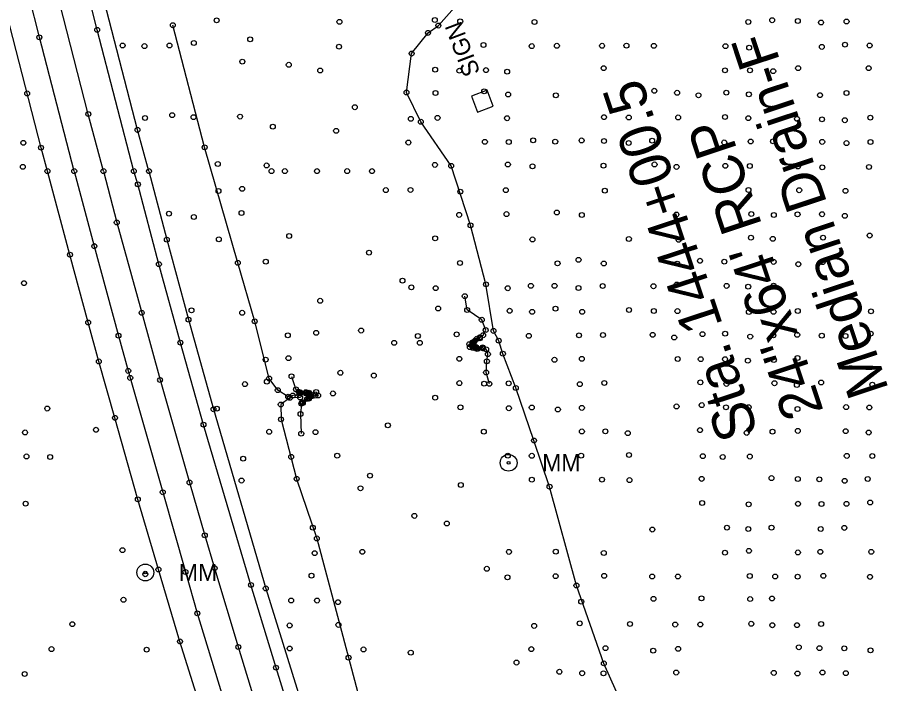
# Model space of a CAD drawing. Extents: x 20503438 to 20508873, y 7964251 to 7984667.
# Drawn here: x 20505592.1 to 20505946.9, y 7976920.6 to 7977192.3 of the extents above; entities that cross this region are included whole.
import ezdxf

# ---------------------------------------------------------------- set-up
doc = ezdxf.new("R2010")
doc.units = 0
for name, color, linetype in [('SurBreakLine', 7, 'Continuous'), ('SurConcreteSlab', 7, 'Continuous'), ('SurDrainageArrowUp', 7, 'Continuous'), ('SurEdgeRoadPaved', 7, 'Continuous'), ('SurEdgeShoulderPaved', 7, 'Continuous'), ('SurPointsNonDTM', 7, 'Continuous'), ('SurRoadPoints', 7, 'Continuous'), ('SurSurveyPoints', 7, 'Continuous'), ('SurTxtDrainage', 7, 'Continuous')]:
    doc.layers.add(name, color=color, linetype=linetype)

msp = doc.modelspace()

# ---------------------------------------------------------------- linework, layer by layer
at = {"layer": 'SurBreakLine'}
for points in [[(20505627.16, 7977129.6), (20505621, 7977152.86), (20505604.98, 7977215.01)], [(20505627.16, 7977129.6), (20505632.6, 7977108.64), (20505642.78, 7977071.79), (20505650.26, 7977044.44), (20505662.27, 7977002.64), (20505668.49, 7976981.08), (20505672.51, 7976967.67), (20505682.17, 7976935.56), (20505689.5, 7976911.63)], [(20505784.52, 7977042.85), (20505783.2, 7977047.48), (20505783.52, 7977052.06), (20505783.93, 7977054.98), (20505783.23, 7977056.95), (20505781.78, 7977057.35), (20505779.53, 7977057.07), (20505777.83, 7977057.46), (20505776.58, 7977057.82), (20505776.33, 7977059.03), (20505777.62, 7977059.8), (20505779.41, 7977061.23), (20505780.72, 7977061.88), (20505781.97, 7977062.67), (20505783.02, 7977064.79), (20505781.42, 7977068.98), (20505775.49, 7977072.98), (20505774.5, 7977078.6)], [(20505703.86, 7977045.89), (20505705.66, 7977040.61), (20505706.75, 7977039.62), (20505707.23, 7977039.41), (20505709.74, 7977039.48), (20505711, 7977039.27), (20505713.91, 7977039.54), (20505714.72, 7977038.09), (20505713.52, 7977038.02), (20505712.02, 7977037.77), (20505710.95, 7977036.83), (20505708.44, 7977035.03), (20505707.88, 7977034.78), (20505707.54, 7977030.55), (20505707.82, 7977022.56)]]:
    msp.add_lwpolyline(points, dxfattribs=at)
at = {"layer": 'SurConcreteSlab'}
for points in [[(20505781.78, 7977057.76), (20505779.2, 7977057.84), (20505778.28, 7977058.25), (20505777.84, 7977058.9), (20505778.13, 7977059.52), (20505780.62, 7977061.42), (20505780.54, 7977061.59), (20505778.63, 7977060.38), (20505777.95, 7977059.64), (20505777.68, 7977058.92), (20505777.91, 7977058.29), (20505778.53, 7977057.75), (20505779.54, 7977057.44), (20505781.82, 7977057.49)], [(20505707.23, 7977039.07), (20505709.48, 7977039.08), (20505710.47, 7977038.91), (20505711.08, 7977038.48), (20505711.05, 7977038), (20505710.84, 7977037.38), (20505710.22, 7977036.7), (20505708.23, 7977035.42), (20505708.39, 7977035.2), (20505710.83, 7977036.95), (20505711.26, 7977037.65), (20505711.23, 7977038.59), (20505710.57, 7977039.1), (20505709.82, 7977039.27), (20505707.52, 7977039.36)]]:
    msp.add_lwpolyline(points, close=True, dxfattribs=at)
at = {"layer": 'SurDrainageArrowUp'}
for points in [[(20505841.57, 7976905.79), (20505831.2, 7976928.87), (20505820.02, 7976960.63), (20505809.08, 7977000.91), (20505802.72, 7977019.77), (20505795.33, 7977041.18), (20505790.04, 7977055.14), (20505788.34, 7977060.44), (20505786.23, 7977064.44), (20505783.14, 7977083.44), (20505776.83, 7977107.5), (20505768.94, 7977131.75), (20505756.6, 7977149.72), (20505750.73, 7977161.63), (20505752.84, 7977177.52), (20505759.52, 7977185.95), (20505763.74, 7977188.93), (20505777.8, 7977204.89)], [(20505707.08, 7977038.35), (20505704.42, 7977038.11), (20505702.5, 7977037.59), (20505698.25, 7977040.29), (20505694.71, 7977045.04), (20505688.86, 7977068.33), (20505681.98, 7977092.2), (20505668.42, 7977139.31), (20505655.45, 7977189.07)], [(20505707.4, 7977037.27), (20505703.17, 7977037.15), (20505699.48, 7977034.43), (20505699.58, 7977028.38), (20505705.95, 7977004.1), (20505714.17, 7976979.83), (20505727.11, 7976931.22), (20505739.64, 7976883.92), (20505750.55, 7976861.92), (20505767.66, 7976808.37), (20505782.7, 7976762.01), (20505813.56, 7976666.44), (20505830.86, 7976618.86), (20505849.64, 7976572.31), (20505867.43, 7976526.9), (20505886.99, 7976479.14), (20505905.22, 7976432.12), (20505914.25, 7976410.54), (20505924.33, 7976390.07)]]:
    msp.add_lwpolyline(points, dxfattribs=at)
at = {"layer": 'SurEdgeRoadPaved'}
for points in [[(20505639.58, 7977129.6), (20505624.63, 7977187.2), (20505615.58, 7977223)], [(20505615.26, 7977129.6), (20505601.04, 7977184.16), (20505592.64, 7977217.57)], [(20505667.23, 7976909.32), (20505658.37, 7976937.83), (20505649.59, 7976967.17), (20505641.18, 7976995.74), (20505631.87, 7977028.97), (20505625.28, 7977051.99), (20505620.94, 7977067.88), (20505613.51, 7977095.5), (20505604.33, 7977129.6)], [(20505615.26, 7977129.6), (20505623.45, 7977099.02), (20505633.31, 7977062.48), (20505637.29, 7977048.14), (20505638.09, 7977045.27), (20505651.36, 7976998.65), (20505660.6, 7976966.16), (20505665.45, 7976949.3), (20505675.3, 7976916.84), (20505683.04, 7976892.36), (20505688.19, 7976876.04), (20505701.22, 7976835.1), (20505711.07, 7976804.73), (20505720.51, 7976776.33), (20505734.63, 7976734.41), (20505745.53, 7976702.88), (20505759.33, 7976663.75), (20505771.44, 7976629.94), (20505784.37, 7976595.48), (20505797.7, 7976560.8), (20505811.46, 7976525.6), (20505854.48, 7976420.23), (20505870.79, 7976380.67)], [(20505888.02, 7976400.52), (20505875.61, 7976430.87), (20505858.33, 7976472.87), (20505843.45, 7976509.59), (20505829.21, 7976545.44), (20505815.32, 7976581.21), (20505788.67, 7976653.43), (20505776.13, 7976688.41), (20505761.74, 7976729.52), (20505752.69, 7976755.73), (20505741.62, 7976788.54), (20505730.6, 7976822.27), (20505708.77, 7976891.06), (20505697.53, 7976927.13), (20505687.33, 7976960.85), (20505667.97, 7977026.21), (20505658.55, 7977059.63), (20505649.78, 7977091.67), (20505641.23, 7977124.22), (20505639.58, 7977129.6)]]:
    msp.add_lwpolyline(points, dxfattribs=at)
at = {"layer": 'SurEdgeShoulderPaved'}
for points in [[(20505645.74, 7977129.6), (20505641.05, 7977146.39), (20505623.31, 7977215.43)], [(20505604.33, 7977129.6), (20505601.72, 7977139.15), (20505583.71, 7977209.07)], [(20505645.74, 7977129.6), (20505653, 7977101.66), (20505661.85, 7977069.03), (20505672.05, 7977032.49), (20505693.36, 7976959.44), (20505711.05, 7976902.57), (20505727.57, 7976849.37), (20505739.42, 7976813.17), (20505751.74, 7976776.5), (20505761.39, 7976748.39), (20505765.21, 7976737.3), (20505776.34, 7976705.45), (20505803.39, 7976629.54), (20505816.72, 7976594.21), (20505830.99, 7976557.36), (20505845.1, 7976521.55), (20505859.09, 7976486.97), (20505874.74, 7976448.5), (20505889.98, 7976411.65), (20505895.55, 7976397.9)]]:
    msp.add_lwpolyline(points, dxfattribs=at)
at = {"layer": 'SurPointsNonDTM'}
msp.add_circle((20505737.41, 7977046.23), 1, dxfattribs=at)
at = {"layer": 'SurRoadPoints'}
msp.add_lwpolyline([(20505784.83, 7977159.33), (20505784.83, 7977159.33), (20505783.61, 7977162.53), (20505777.21, 7977160.09), (20505779.65, 7977153.69), (20505786.05, 7977156.13), (20505784.83, 7977159.33)], dxfattribs=at)
for centre, radius in [((20505792.37, 7977010.68), 3.43), ((20505792.37, 7977010.68), 0.571), ((20505644.24, 7976965.95), 3.43), ((20505644.24, 7976965.95), 0.571)]:
    msp.add_circle(centre, radius, dxfattribs=at)
at = {"layer": 'SurSurveyPoints'}
for centre in [(20505673.32, 7977191.06), (20505723.4, 7977190.45), (20505762.3, 7977191.18), (20505772.65, 7977190.67), (20505802.93, 7977190.41), (20505890.09, 7977190.41), (20505899.83, 7977191.11), (20505910.29, 7977190.79), (20505919.77, 7977190.19), (20505930.17, 7977190.59), (20505624.63, 7977187.2), (20505655.45, 7977189.07), (20505763.74, 7977188.93), (20505601.04, 7977184.16), (20505687.01, 7977183.33), (20505759.52, 7977185.95), (20505634.99, 7977180.82), (20505643.88, 7977180.56), (20505654.09, 7977180.82), (20505664.02, 7977181.85), (20505723.21, 7977180.31), (20505782.1, 7977181.03), (20505801.8, 7977180.57), (20505812.07, 7977180.7), (20505830.48, 7977180.7), (20505840.42, 7977180.76), (20505851.62, 7977180.67), (20505880.78, 7977180.53), (20505890.46, 7977179.93), (20505920.09, 7977180.24), (20505929.55, 7977181.15), (20505939.57, 7977180.81), (20505752.84, 7977177.52), (20505683.79, 7977174.24), (20505702.74, 7977172.96), (20505715.52, 7977170.61), (20505762.42, 7977170.95), (20505772.29, 7977170.52), (20505783.16, 7977170.78), (20505791.79, 7977170.14), (20505831.12, 7977171.58), (20505880.6, 7977170.68), (20505890.77, 7977170.69), (20505900.28, 7977170.36), (20505910.41, 7977171.58), (20505939.19, 7977171.55), (20505596.06, 7977161.26), (20505750.73, 7977161.63), (20505762.56, 7977161.44), (20505782.41, 7977162.12), (20505851.79, 7977162.36), (20505861.08, 7977161.54), (20505881.14, 7977161.59), (20505930.16, 7977161.43), (20505792.18, 7977160.82), (20505811.66, 7977160.49), (20505869.8, 7977160.52), (20505890.35, 7977160.88), (20505919.33, 7977160.55), (20505729.67, 7977155.64), (20505621, 7977152.86), (20505644.14, 7977151.26), (20505655.18, 7977152.41), (20505663.9, 7977151.59), (20505682.88, 7977151.82), (20505752.51, 7977150.89), (20505763.4, 7977151.29), (20505791.74, 7977151.16), (20505831.26, 7977151.58), (20505841.37, 7977151.44), (20505861.51, 7977151.48), (20505880.6, 7977151.65), (20505890.1, 7977151.17), (20505909.95, 7977150.91), (20505920.14, 7977150.69), (20505939.87, 7977151.4), (20505696.22, 7977147.73), (20505756.6, 7977149.72), (20505929.47, 7977150.34), (20505641.05, 7977146.39), (20505722.04, 7977146), (20505594.5, 7977141.12), (20505751.51, 7977141.23), (20505782.71, 7977141.54), (20505792.43, 7977141.45), (20505802.4, 7977142.16), (20505811.38, 7977141.62), (20505822.14, 7977142.11), (20505831.26, 7977141.86), (20505841.31, 7977141.06), (20505850.91, 7977141.99), (20505880.31, 7977141.29), (20505891.07, 7977141.68), (20505900.18, 7977141.72), (20505920.25, 7977141.5), (20505930.16, 7977141.02), (20505939.95, 7977141.46), (20505601.72, 7977139.15), (20505668.42, 7977139.31), (20505594.32, 7977131.33), (20505604.33, 7977129.6), (20505604.33, 7977129.6), (20505615.26, 7977129.6), (20505615.26, 7977129.6), (20505627.16, 7977129.6), (20505627.16, 7977129.6), (20505639.58, 7977129.6), (20505639.58, 7977129.6), (20505645.74, 7977129.6), (20505645.74, 7977129.6), (20505673.78, 7977132.52), (20505693.7, 7977131.91), (20505695.68, 7977129.6), (20505695.68, 7977129.6), (20505701.16, 7977129.6), (20505701.16, 7977129.6), (20505714.24, 7977129.6), (20505714.24, 7977129.6), (20505726.55, 7977129.6), (20505726.56, 7977129.6), (20505736.67, 7977129.6), (20505736.67, 7977129.6), (20505762.33, 7977132.13), (20505768.94, 7977131.75), (20505792.09, 7977132.3), (20505802.13, 7977131.56), (20505831.05, 7977131.81), (20505851.89, 7977132.31), (20505860.86, 7977131.3), (20505880.75, 7977131.74), (20505890.73, 7977131.69), (20505910.35, 7977131.5), (20505920.27, 7977131.14), (20505939.33, 7977131.29), (20505641.23, 7977124.22), (20505683.7, 7977122.37), (20505674.08, 7977121.48), (20505742.31, 7977121.86), (20505752.37, 7977121.92), (20505772.66, 7977121.2), (20505791.24, 7977121.83), (20505831.6, 7977121.62), (20505890.19, 7977121.87), (20505910.87, 7977121.79), (20505929.72, 7977121.54), (20505653.88, 7977112.25), (20505683.46, 7977112.51), (20505772.21, 7977111.74), (20505791.52, 7977112.06), (20505812.05, 7977112.7), (20505822.22, 7977111.7), (20505860.79, 7977111.9), (20505891.34, 7977112.08), (20505900.5, 7977111.68), (20505910.2, 7977111.95), (20505920.18, 7977112.01), (20505632.6, 7977108.64), (20505664.01, 7977110.91), (20505929.47, 7977111.35), (20505776.83, 7977107.5), (20505653, 7977101.66), (20505674.23, 7977101.8), (20505702.91, 7977103.14), (20505762.41, 7977102.16), (20505802.09, 7977101.74), (20505841.42, 7977101.94), (20505861.72, 7977101.59), (20505891.18, 7977102.43), (20505900.08, 7977101.97), (20505920.59, 7977102.46), (20505939.58, 7977103.31), (20505623.45, 7977099.02), (20505613.51, 7977095.5), (20505735.47, 7977096.35), (20505649.78, 7977091.67), (20505681.98, 7977092.2), (20505693.35, 7977092.68), (20505772.54, 7977092.13), (20505812.34, 7977091.97), (20505820.9, 7977093.42), (20505831.17, 7977091.93), (20505861.09, 7977091.85), (20505870.41, 7977093.03), (20505880.32, 7977092.67), (20505900.42, 7977092.57), (20505910.51, 7977091.62), (20505920.42, 7977092.47), (20505594.78, 7977083.89), (20505749.09, 7977084.93), (20505783.14, 7977083.44), (20505860.93, 7977083.34), (20505752.73, 7977082.2), (20505762.64, 7977081.87), (20505792.01, 7977081.83), (20505801.47, 7977082.8), (20505811.12, 7977082.8), (20505820.89, 7977081.93), (20505830.72, 7977082.74), (20505851.43, 7977082.65), (20505881.26, 7977082.78), (20505890.07, 7977082.46), (20505900.43, 7977082.91), (20505715.55, 7977076.73), (20505774.5, 7977078.6), (20505663.06, 7977072.8), (20505763.64, 7977073.57), (20505775.49, 7977072.98), (20505792.8, 7977072.65), (20505811.51, 7977073.51), (20505841.48, 7977072.97), (20505851.58, 7977072.57), (20505861.2, 7977072.52), (20505910.27, 7977072.56), (20505642.78, 7977071.79), (20505661.85, 7977069.03), (20505683.72, 7977071.84), (20505781.42, 7977068.98), (20505801.95, 7977072.22), (20505822.36, 7977072.23), (20505890.33, 7977072.17), (20505900.41, 7977072.2), (20505940.15, 7977072.43), (20505620.94, 7977067.88), (20505688.86, 7977068.33), (20505633.31, 7977062.48), (20505702.37, 7977062.65), (20505713.9, 7977063.65), (20505732.22, 7977064.58), (20505755.38, 7977062.38), (20505771.18, 7977063.02), (20505780.72, 7977061.88), (20505781.97, 7977062.67), (20505783.02, 7977064.79), (20505786.23, 7977064.44), (20505800.6, 7977062.44), (20505821.09, 7977062.65), (20505830.84, 7977062.75), (20505851.12, 7977062.84), (20505871.43, 7977063.12), (20505880.64, 7977063.3), (20505890.89, 7977062.12), (20505900.34, 7977062.64), (20505910.05, 7977062.87), (20505920.06, 7977062.48), (20505929.72, 7977062.35), (20505940, 7977063.33), (20505658.55, 7977059.63), (20505745.71, 7977059.58), (20505756.16, 7977059.58), (20505776.33, 7977059.03), (20505777.62, 7977059.8), (20505777.68, 7977058.92), (20505777.84, 7977058.9), (20505777.95, 7977059.64), (20505778.13, 7977059.52), (20505778.63, 7977060.38), (20505779.41, 7977061.23), (20505780.54, 7977061.59), (20505780.62, 7977061.42), (20505788.34, 7977060.44), (20505859.9, 7977061.74), (20505776.58, 7977057.82), (20505777.83, 7977057.46), (20505777.91, 7977058.29), (20505778.28, 7977058.25), (20505778.53, 7977057.75), (20505779.2, 7977057.84), (20505779.53, 7977057.07), (20505779.54, 7977057.44), (20505781.78, 7977057.76), (20505781.78, 7977057.35), (20505781.82, 7977057.49), (20505783.23, 7977056.95), (20505783.93, 7977054.98), (20505790.04, 7977055.14), (20505625.28, 7977051.99), (20505693.3, 7977052.74), (20505702.6, 7977053.32), (20505772.29, 7977053.04), (20505783.52, 7977052.06), (20505811.05, 7977052.68), (20505822.23, 7977053.05), (20505861.33, 7977052.99), (20505870.71, 7977052.93), (20505880.63, 7977052.88), (20505889.95, 7977052.28), (20505900.55, 7977052.59), (20505910.15, 7977053.41), (20505637.29, 7977048.14), (20505638.09, 7977045.27), (20505650.26, 7977044.44), (20505694.71, 7977045.04), (20505703.86, 7977045.89), (20505723.78, 7977047.38), (20505783.2, 7977047.48), (20505684.87, 7977042.75), (20505693.79, 7977043.73), (20505705.66, 7977040.61), (20505772.3, 7977043.16), (20505782.39, 7977042.92), (20505784.52, 7977042.85), (20505792.41, 7977043.07), (20505795.33, 7977041.18), (20505821.41, 7977042.73), (20505831.41, 7977043.22), (20505870.57, 7977043.45), (20505881.19, 7977042.82), (20505900.76, 7977043.11), (20505909.88, 7977042.38), (20505919.82, 7977043.39), (20505940.68, 7977042.52), (20505698.25, 7977040.29), (20505702.5, 7977037.59), (20505703.17, 7977037.15), (20505704.42, 7977038.11), (20505706.75, 7977039.62), (20505707.08, 7977038.35), (20505707.23, 7977039.41), (20505707.23, 7977039.07), (20505707.4, 7977037.27), (20505707.52, 7977039.36), (20505709.48, 7977039.08), (20505709.74, 7977039.48), (20505709.82, 7977039.27), (20505710.47, 7977038.91), (20505710.57, 7977039.1), (20505710.84, 7977037.38), (20505711, 7977039.27), (20505711.05, 7977038), (20505711.08, 7977038.48), (20505711.23, 7977038.59), (20505711.26, 7977037.65), (20505712.02, 7977037.77), (20505713.52, 7977038.02), (20505713.91, 7977039.54), (20505714.72, 7977038.09), (20505720.75, 7977038.95), (20505762.44, 7977037.2), (20505699.48, 7977034.43), (20505707.88, 7977034.78), (20505708.23, 7977035.42), (20505708.39, 7977035.2), (20505708.44, 7977035.03), (20505710.22, 7977036.7), (20505710.83, 7977036.95), (20505710.95, 7977036.83), (20505860.86, 7977033.64), (20505871.11, 7977034.19), (20505604.27, 7977032.77), (20505672.05, 7977032.49), (20505673.42, 7977032.75), (20505707.54, 7977030.55), (20505772.73, 7977033.26), (20505792.5, 7977032.91), (20505801.81, 7977033.2), (20505812.48, 7977032.39), (20505822.25, 7977033.04), (20505881, 7977033.3), (20505890.24, 7977033.36), (20505910.19, 7977032.61), (20505929.97, 7977033.37), (20505939.44, 7977033.22), (20505631.87, 7977028.97), (20505699.58, 7977028.38), (20505595.21, 7977023.04), (20505624.14, 7977024.13), (20505667.97, 7977026.21), (20505694.73, 7977023.31), (20505713.62, 7977023.14), (20505743.15, 7977025.95), (20505782.29, 7977023.37), (20505822.26, 7977023.46), (20505831.83, 7977023.49), (20505870.42, 7977023.99), (20505889.45, 7977022.85), (20505899.97, 7977023.34), (20505910.31, 7977023.66), (20505929.81, 7977023.56), (20505939.2, 7977022.98), (20505707.82, 7977022.56), (20505802.72, 7977019.77), (20505840.95, 7977022.75), (20505595.81, 7977013.25), (20505605.45, 7977013.03), (20505684.16, 7977012.36), (20505703.7, 7977013.07), (20505722.5, 7977013.55), (20505792.04, 7977013.59), (20505801.81, 7977013.54), (20505821.92, 7977013.59), (20505841.45, 7977013.85), (20505871.56, 7977013.38), (20505879.68, 7977013.05), (20505890.73, 7977013.21), (20505930.26, 7977013.47), (20505940.66, 7977013.43), (20505735.86, 7977005.42), (20505662.27, 7977002.64), (20505683.49, 7977003.41), (20505705.95, 7977004.1), (20505772.9, 7977001.61), (20505801.83, 7977003.76), (20505830.47, 7977003.81), (20505841.66, 7977003.61), (20505871.08, 7977004.09), (20505899.55, 7977004.43), (20505910.3, 7977004.08), (20505919.05, 7977003.93), (20505929.4, 7977003.3), (20505938.8, 7977004.08), (20505651.36, 7976998.65), (20505731.99, 7977000.28), (20505809.08, 7977000.91), (20505641.18, 7976995.74), (20505939.81, 7976994.46), (20505595.44, 7976994), (20505871.3, 7976994.28), (20505890.25, 7976993.75), (20505910.36, 7976993.96), (20505919.97, 7976993.88), (20505930.15, 7976993.94), (20505753.96, 7976989.01), (20505712.56, 7976984.22), (20505767.2, 7976985.93), (20505881.39, 7976984.22), (20505899.59, 7976984.21), (20505929.27, 7976984.12), (20505668.49, 7976981.08), (20505850.96, 7976983.43), (20505890.1, 7976983.66), (20505919.63, 7976983.68), (20505714.17, 7976979.83), (20505634.91, 7976975.03), (20505713.29, 7976973.8), (20505732.73, 7976974.36), (20505792.51, 7976974.33), (20505811.59, 7976974.41), (20505831.18, 7976973.91), (20505880.58, 7976974), (20505890.36, 7976974.76), (20505910.34, 7976974.12), (20505919.46, 7976974.37), (20505940.24, 7976974.35), (20505649.59, 7976967.17), (20505660.6, 7976966.16), (20505672.51, 7976967.67), (20505783.49, 7976967.45), (20505644.25, 7976965.22), (20505712, 7976964.66), (20505791.9, 7976963.97), (20505811.54, 7976964.45), (20505831.33, 7976964.56), (20505850.91, 7976964.3), (20505861.41, 7976964.32), (20505890.7, 7976964.51), (20505901.07, 7976964.29), (20505910.23, 7976964.21), (20505920.72, 7976964.57), (20505939.72, 7976964.13), (20505687.33, 7976960.85), (20505693.36, 7976959.44), (20505820.02, 7976960.63), (20505635.32, 7976954.82), (20505703.71, 7976954.5), (20505714.27, 7976954.48), (20505722.81, 7976953.82), (20505821.98, 7976954.04), (20505851.44, 7976955.18), (20505871.02, 7976955.39), (20505890.87, 7976955.1), (20505899.75, 7976955.35), (20505665.45, 7976949.3), (20505614.49, 7976944.88), (20505821.37, 7976945.22), (20505841.88, 7976944.94), (20505891.32, 7976945.04), (20505919.79, 7976944.94), (20505703.08, 7976944.36), (20505722.98, 7976944.56), (20505802.8, 7976944.16), (20505860.32, 7976944.7), (20505870.53, 7976944.74), (20505899.92, 7976944.44), (20505909.96, 7976944.45), (20505658.37, 7976937.83), (20505606.01, 7976934.7), (20505644.78, 7976934.46), (20505682.17, 7976935.56), (20505703.09, 7976934.95), (20505733.2, 7976934.57), (20505801.65, 7976934.71), (20505831.87, 7976935.07), (20505861.48, 7976934.8), (20505910.72, 7976935.45), (20505919.1, 7976935.07), (20505929.24, 7976935.02), (20505939.96, 7976934.18), (20505727.11, 7976931.22), (20505752.48, 7976933.27), (20505851.35, 7976934.08), (20505697.53, 7976927.13), (20505795.6, 7976929.21), (20505831.2, 7976928.87), (20505595.04, 7976924.55), (20505813.08, 7976925.46), (20505822.35, 7976924.86), (20505831.05, 7976924.84), (20505860.72, 7976925.14), (20505900.48, 7976924.99), (20505910.13, 7976924.77), (20505920.33, 7976925.15), (20505929.86, 7976924.87)]:
    msp.add_circle(centre, 1, dxfattribs=at)

# ---------------------------------------------------------------- texts
at = {"layer": 'SurRoadPoints'}
for s, rotation, p in [('SIGN', 110.9142, (20505780.9, 7977169.83)), ('MM', 360, (20505806.08, 7977007.19)), ('MM', 360, (20505657.95, 7976962.46))]:
    msp.add_text(s, height=6.995, rotation=rotation, dxfattribs=at).set_placement(p)
at = {"layer": 'SurTxtDrainage'}
for s, p in [('Median Drain-F', (20505947.48, 7977040.53)), ('Sta. 1444+00.5', (20505894.31, 7977022.94)), ('24"x64\' RCP', (20505920.89, 7977031.73))]:
    msp.add_text(s, height=16.8, rotation=108.2983, dxfattribs=at).set_placement(p)

doc.saveas('drawing.dxf')
